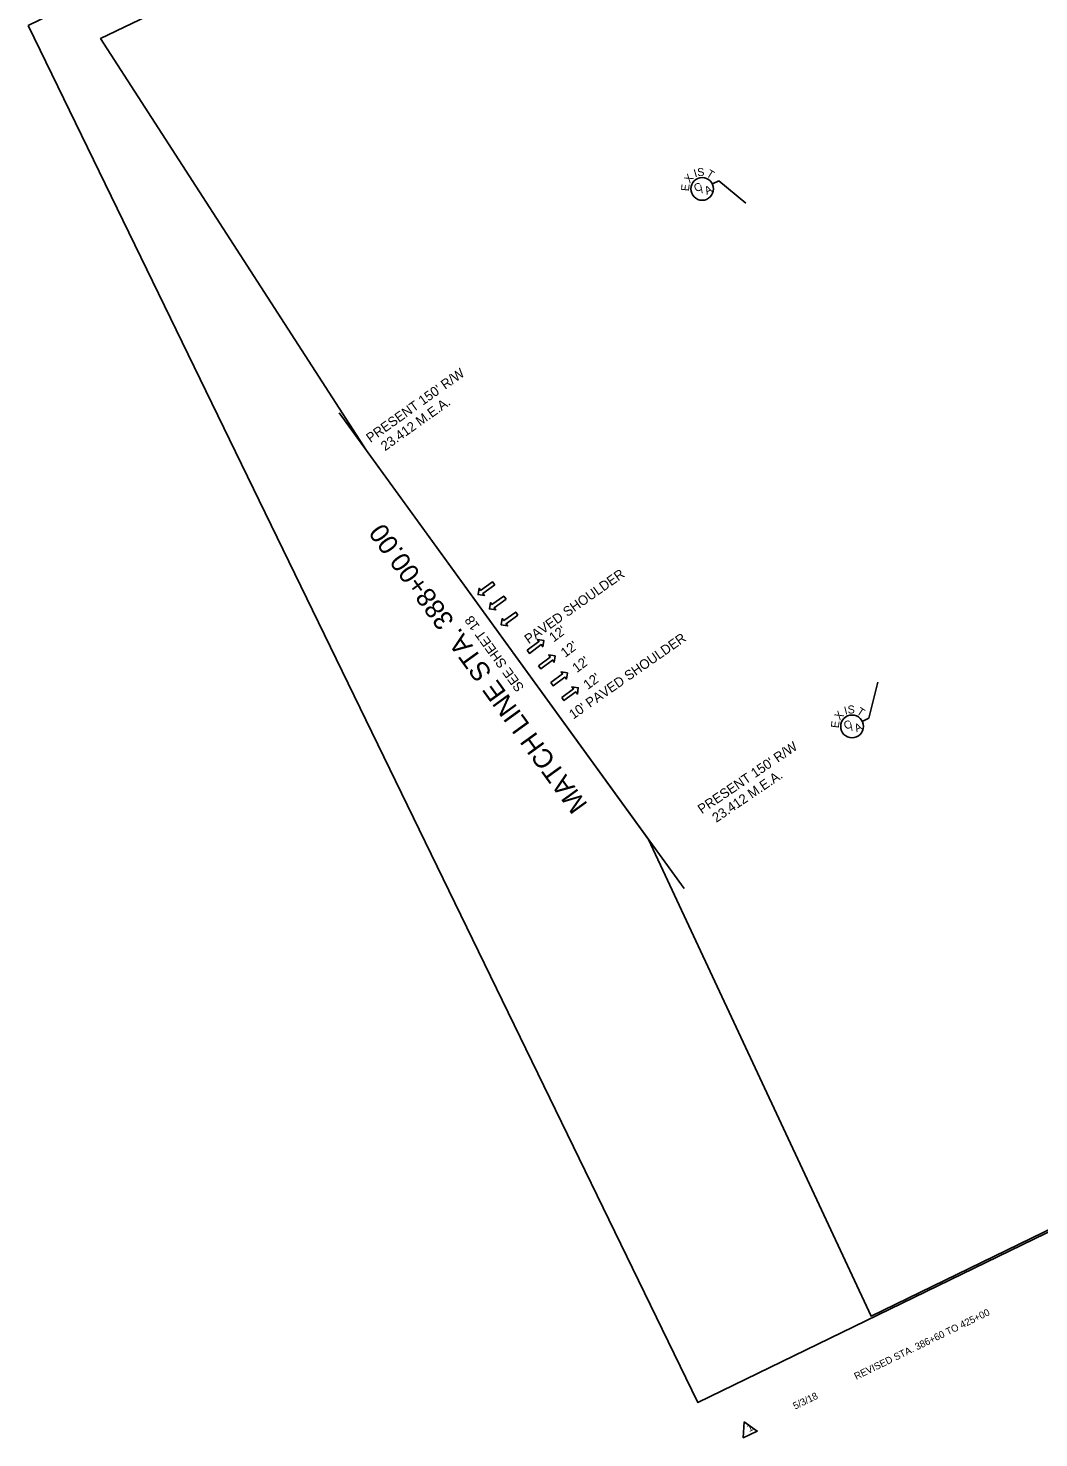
# Model space of a CAD drawing. Extents: x 1616869 to 1620470, y 1100482 to 1103335.
# Drawn here: x 1616869 to 1617500, y 1100482 to 1101363 of the extents above; entities that cross this region are included whole.
import ezdxf

# ---------------------------------------------------------------- set-up
doc = ezdxf.new("R2010")
doc.units = 0
for name, color, linetype in [('Level 2', 7, 'Continuous'), ('Level 4', 7, 'Continuous'), ('RD_PD_DR_Pipe', 7, 'Continuous'), ('RD_SHT_MatchLine', 7, 'Continuous'), ('RD_SHT_Misc2', 7, 'Continuous'), ('RD_SHT_TX', 7, 'Continuous'), ('RD_TX_RW', 7, 'Continuous')]:
    doc.layers.add(name, color=color, linetype=linetype)

msp = doc.modelspace()

# ---------------------------------------------------------------- linework, layer by layer
at = {"layer": 'Level 2'}
msp.add_lwpolyline([(1616868.78, 1101364.63), (1618375.15, 1102097.07), (1618793.41, 1101236.86), (1617287.04, 1100504.42)], close=True, dxfattribs=at)
at = {"layer": 'Level 4'}
msp.add_lwpolyline([(1617080.14, 1101099.03), (1617256.2, 1100856.12), (1617395.1, 1100558.35), (1618700.82, 1101193.66), (1618573.12, 1101494.1), (1618454.8, 1101769.78), (1618339.83, 1102037.66), (1618182.95, 1101960.1), (1618167.86, 1101990.6), (1616961.35, 1101407.95), (1616972.59, 1101384.68), (1616914.03, 1101356.41)], close=True, dxfattribs=at)
msp.add_lwpolyline([(1617080.14, 1101099.03), (1617256.2, 1100856.12), (1617395.1, 1100558.35), (1618700.82, 1101193.66), (1618573.12, 1101494.1), (1618454.8, 1101769.78), (1618339.83, 1102037.66), (1618182.95, 1101960.1), (1618167.86, 1101990.6), (1616961.35, 1101407.95), (1616972.59, 1101384.68), (1616914.03, 1101356.41)], close=True, dxfattribs=at)
at = {"layer": 'RD_PD_DR_Pipe'}
for p, q in [((1617296.04, 1101265.6), (1617300.16, 1101267.6)), ((1617300.16, 1101267.6), (1617316.93, 1101253.59)), ((1617393.72, 1100931.88), (1617399.32, 1100954.48)), ((1617389.6, 1100929.88), (1617393.72, 1100931.88))]:
    msp.add_line(p, q, dxfattribs=at)
for centre in [(1617289.67, 1101262.5), (1617383.23, 1100926.78)]:
    msp.add_circle(centre, 7.08, dxfattribs=at)
at = {"layer": 'RD_SHT_MatchLine'}
msp.add_line((1617278.43, 1100825.46), (1617063.04, 1101122.63), dxfattribs=at)
at = {"layer": 'RD_SHT_Misc2'}
for points in [[(1617160.12, 1101015.18), (1617158.71, 1101017.12), (1617151.29, 1101011.73), (1617150.33, 1101013.04), (1617149.71, 1101009.09), (1617153.66, 1101008.47), (1617152.7, 1101009.79)], [(1617167.2, 1101006.27), (1617165.79, 1101008.21), (1617158.37, 1101002.82), (1617157.41, 1101004.13), (1617156.79, 1101000.18), (1617160.74, 1100999.56), (1617159.78, 1101000.87)], [(1617174.64, 1100996.27), (1617173.22, 1100998.21), (1617165.81, 1100992.81), (1617164.85, 1100994.13), (1617164.23, 1100990.18), (1617168.18, 1100989.55), (1617167.22, 1100990.87)], [(1617180.33, 1100974.31), (1617181.75, 1100972.38), (1617189.13, 1100977.83), (1617190.1, 1100976.52), (1617190.69, 1100980.48), (1617186.74, 1100981.07), (1617187.7, 1100979.76)], [(1617187.46, 1100964.66), (1617188.88, 1100962.73), (1617196.26, 1100968.18), (1617197.23, 1100966.87), (1617197.82, 1100970.83), (1617193.87, 1100971.42), (1617194.83, 1100970.11)], [(1617195.09, 1100954.11), (1617196.51, 1100952.18), (1617203.92, 1100957.58), (1617204.88, 1100956.27), (1617205.49, 1100960.22), (1617201.54, 1100960.84), (1617202.5, 1100959.52)], [(1617201.92, 1100944.83), (1617203.34, 1100942.89), (1617210.75, 1100948.3), (1617211.71, 1100946.98), (1617212.32, 1100950.93), (1617208.37, 1100951.55), (1617209.33, 1100950.23)]]:
    msp.add_lwpolyline(points, close=True, dxfattribs=at)
at = {"layer": 'RD_SHT_TX'}
msp.add_lwpolyline([(1617315.86, 1100492.37), (1617315.32, 1100482.4), (1617324.04, 1100486.64)], close=True, dxfattribs=at)

# ---------------------------------------------------------------- texts
at = {"layer": 'RD_PD_DR_Pipe'}
for s, rotation, p in [('X', 51.02398, (1617281.9, 1101265.75)), ('I', 15.86251, (1617285.19, 1101269.63)), ('S', 4.14202, (1617286.73, 1101270.39)), ('T', 328.98055, (1617291.81, 1101270.65)), ('E', 84.5111, (1617281.4, 1101260.92)), ('C', 25.92721, (1617285.93, 1101260.25)), ('/', 25.92721, (1617289.51, 1101259.65)), ('A', 25.92721, (1617292.55, 1101258.73)), ('X', 49.07183, (1617375.58, 1100930.29)), ('I', 13.91036, (1617379, 1100934.05)), ('S', 2.18987, (1617380.56, 1100934.76)), ('T', 327.02839, (1617385.65, 1100934.84)), ('E', 82.55895, (1617374.91, 1100925.48)), ('C', 25.92721, (1617379.48, 1100924.52)), ('/', 25.92721, (1617383.07, 1100923.92)), ('A', 25.92721, (1617386.1, 1100923.01))]:
    msp.add_text(s, height=5, rotation=rotation, dxfattribs=at).set_placement(p)
at = {"layer": 'RD_SHT_MatchLine'}
for s, height, p in [('MATCH LINE STA. 388+00.00', 12, (1617218.51, 1100878)), ('SEE SHEET 18', 6, (1617178.77, 1100951.07))]:
    msp.add_text(s, height=height, rotation=125.93545, dxfattribs=at).set_placement(p)
at = {"layer": 'RD_SHT_TX'}
for s, height, rotation, p in [(' PAVED SHOULDER', 6, 35.15283, (1617179.52, 1100976.75)), ("12'", 6, 37.08712, (1617196.92, 1100979.12)), ("12'", 6, 37.08712, (1617204.15, 1100969.55)), ("10' PAVED SHOULDER", 6, 34.92906, (1617209.17, 1100930.98)), ("12'", 6, 37.08712, (1617211.39, 1100959.98)), ("12'", 6, 37.08712, (1617218.29, 1100949.5)), ('REVISED STA. 386+60 TO 425+00', 4.4, 25.93046, (1617385.88, 1100518.53)), ('5/3/18', 4.4, 25.93046, (1617347.71, 1100499.97)), ('1', 4.4, 25.93046, (1617319, 1100486.01))]:
    msp.add_text(s, height=height, rotation=rotation, dxfattribs=at).set_placement(p)
at = {"layer": 'RD_TX_RW'}
for s, rotation, p in [("PRESENT 150' R/W ", 35.52169, (1617082.54, 1101103.71)), ('  23.412 M.E.A.', 35.52169, (1617088.06, 1101095.98)), ("PRESENT 150' R/W ", 34.1732, (1617289.46, 1100871.83)), ('  23.412 M.E.A.', 34.1732, (1617294.79, 1100863.97))]:
    msp.add_text(s, height=6, rotation=rotation, dxfattribs=at).set_placement(p)

doc.saveas('drawing.dxf')
